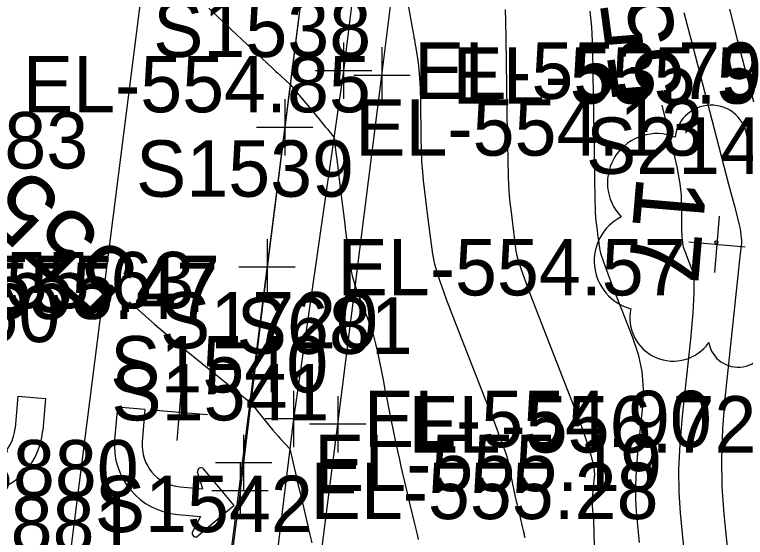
# Model space of a CAD drawing. Extents: x 1724534 to 1727318, y 657156 to 660047.
# Drawn here: x 1725449.4 to 1725501.3, y 658904.2 to 658941.3 of the extents above; entities that cross this region are included whole.
import ezdxf

# ---------------------------------------------------------------- set-up
doc = ezdxf.new("R2010")
doc.units = 0
for name, color, linetype in [('SURVEY - CENTERLINE - Preliminary', 7, 'Continuous'), ('SURVEY - CONTOURS - Index with Text', 7, 'Continuous'), ('SURVEY - CONTOURS - Intermediate with optional Text', 7, 'Continuous'), ('SURVEY - DTM - Breaklines - Points - Elevations', 7, 'Continuous'), ('SURVEY - ROADSIDE BARRIERS - Points - Elevations', 7, 'Continuous'), ('SURVEY - ROADSIDE BARRIERS - Points - Locators', 7, 'Continuous'), ('SURVEY - ROADSIDE BARRIERS - Points - Numbers', 7, 'Continuous'), ('SURVEY - ROADSIDE BARRIERS with Text', 7, 'Continuous'), ('SURVEY - TRAFFIC CONTROL - Pavement Marking - Points - Locators', 7, 'Continuous'), ('SURVEY - TRAFFIC CONTROL - Pavement Marking - Points - Numbers', 7, 'Continuous'), ('SURVEY - TRAFFIC CONTROL - Pavement Marking with Text', 7, 'Continuous'), ('SURVEY - TRANSPORTATION - Features', 7, 'Continuous'), ('SURVEY - TRANSPORTATION - Features - Points - Elevations', 7, 'Continuous'), ('SURVEY - TRANSPORTATION - Features - Points - Locators', 7, 'Continuous'), ('SURVEY - TRANSPORTATION - Features - Points - Numbers', 7, 'Continuous'), ('SURVEY - TRANSPORTATION - Roads', 7, 'Continuous'), ('SURVEY - TRANSPORTATION - Roads - Points - Elevations', 7, 'Continuous'), ('SURVEY - TRANSPORTATION - Roads - Points - Locators', 7, 'Continuous'), ('SURVEY - TRANSPORTATION - Roads - Points - Numbers', 7, 'Continuous'), ('SURVEY - VEGETATION - Features - Points - Locators', 7, 'Continuous'), ('SURVEY - VEGETATION - Features - Points - Numbers', 7, 'Continuous'), ('SURVEY - VEGETATION - Features with Text', 7, 'Continuous')]:
    doc.layers.add(name, color=color, linetype=linetype)

msp = doc.modelspace()

# ---------------------------------------------------------------- linework, layer by layer
at = {"layer": 'SURVEY - CENTERLINE - Preliminary'}
msp.add_line((1725473.744, 658974.019), (1725452.779, 658808.398), dxfattribs=at)
msp.add_line((1725473.744, 658974.019), (1725452.779, 658808.398), dxfattribs=at)
msp.add_line((1725473.744, 658974.019), (1725452.779, 658808.398), dxfattribs=at)
at = {"layer": 'SURVEY - CONTOURS - Index with Text'}
for points in [[(1725495.341, 658934.883), (1725495.52, 658934.199), (1725496.034, 658932.156), (1725496.404, 658930.526), (1725496.629, 658929.307), (1725496.71, 658928.501), (1725496.731, 658926.9), (1725496.739, 658926.366), (1725496.748, 658925.965), (1725496.756, 658925.696), (1725496.765, 658925.56), (1725496.788, 658925.373), (1725496.796, 658925.304), (1725496.805, 658925.237), (1725496.813, 658925.171), (1725496.821, 658925.106), (1725496.842, 658924.937), (1725496.866, 658924.836), (1725496.924, 658924.661), (1725497.015, 658924.412), (1725497.14, 658924.089), (1725497.517, 658923.127), (1725497.614, 658922.555), (1725497.621, 658921.56), (1725497.539, 658920.141), (1725497.368, 658918.299), (1725496.791, 658912.822), (1725496.619, 658910.853), (1725496.536, 658909.055), (1725496.541, 658907.427), (1725496.635, 658905.969), (1725497.003, 658902.309)], [(1725457.569, 658920.947), (1725457.88, 658920.671), (1725458.905, 658919.754), (1725459.363, 658919.354), (1725459.97, 658918.841), (1725460.725, 658918.216), (1725461.628, 658917.477), (1725466.188, 658913.767), (1725466.265, 658913.676), (1725466.305, 658913.627), (1725466.33, 658913.596), (1725466.359, 658913.56), (1725466.44, 658913.459), (1725466.495, 658913.392), (1725466.748, 658913.079), (1725466.948, 658912.835), (1725467.543, 658912.104), (1725467.756, 658911.845), (1725467.95, 658911.614), (1725468.124, 658911.413), (1725468.278, 658911.241), (1725468.949, 658910.506), (1725469.428, 658908.472), (1725469.538, 658908.007), (1725469.661, 658907.486), (1725469.947, 658906.27), (1725470.365, 658904.497), (1725470.519, 658903.845)]]:
    msp.add_lwpolyline(points, dxfattribs=at)
at = {"layer": 'SURVEY - CONTOURS - Intermediate with optional Text'}
for points in [[(1725463.207, 658941.77), (1725463.749, 658941.254), (1725464.407, 658940.636), (1725466.316, 658938.85), (1725466.947, 658938.259), (1725467.41, 658937.825), (1725467.704, 658937.549), (1725467.83, 658937.429), (1725467.993, 658937.267), (1725468.073, 658937.192), (1725468.31, 658936.973), (1725468.981, 658936.357), (1725470.7, 658934.301), (1725471.034, 658933.901), (1725471.301, 658933.581), (1725471.5, 658933.342), (1725471.632, 658933.183), (1725472.09, 658932.63), (1725472.111, 658932.501), (1725472.115, 658932.476), (1725472.118, 658932.455), (1725472.121, 658932.399), (1725472.133, 658932.296), (1725472.226, 658931.529), (1725472.308, 658930.865), (1725472.558, 658928.845), (1725472.651, 658928.097), (1725472.741, 658927.366), (1725472.829, 658926.652), (1725472.916, 658925.955), (1725473.142, 658924.12), (1725473.247, 658923.442), (1725473.39, 658922.783), (1725473.571, 658922.144), (1725473.791, 658921.524), (1725474.429, 658919.897), (1725474.656, 658919.275), (1725474.859, 658918.631), (1725475.037, 658917.964), (1725475.191, 658917.274), (1725475.569, 658915.404), (1725475.707, 658914.719), (1725475.839, 658914.067), (1725475.963, 658913.449), (1725476.082, 658912.863), (1725476.388, 658911.346), (1725476.503, 658910.789), (1725476.616, 658910.255), (1725476.729, 658909.745), (1725476.842, 658909.259), (1725477.354, 658907.083), (1725477.455, 658906.657), (1725477.8, 658905.193), (1725477.891, 658904.803), (1725477.98, 658904.429), (1725478.064, 658904.07)], [(1725477.354, 658941.999), (1725477.713, 658939.996), (1725477.746, 658939.815), (1725477.757, 658939.751), (1725477.766, 658939.701), (1725477.79, 658939.55), (1725477.831, 658939.3), (1725477.888, 658938.951), (1725478.062, 658937.886), (1725478.12, 658937.417), (1725478.166, 658936.808), (1725478.198, 658936.061), (1725478.218, 658935.174), (1725478.252, 658932.623), (1725478.272, 658931.713), (1725478.307, 658930.895), (1725478.358, 658930.17), (1725478.422, 658929.539), (1725478.687, 658927.399), (1725478.757, 658926.833), (1725478.825, 658926.281), (1725478.892, 658925.743), (1725479.067, 658924.324), (1725479.22, 658923.615), (1725479.548, 658922.552), (1725480.051, 658921.134), (1725480.728, 658919.361), (1725482.767, 658914.161), (1725483.442, 658912.426), (1725483.937, 658911.122), (1725484.253, 658910.249), (1725484.388, 658909.806), (1725484.511, 658909.2), (1725484.598, 658908.766), (1725484.639, 658908.566), (1725484.677, 658908.376), (1725484.777, 658907.884), (1725484.814, 658907.703), (1725484.851, 658907.53), (1725484.887, 658907.365), (1725484.924, 658907.207), (1725485.02, 658906.797), (1725485.056, 658906.646), (1725485.09, 658906.501), (1725485.234, 658905.888), (1725485.264, 658905.762), (1725485.32, 658905.524), (1725485.347, 658905.412), (1725485.415, 658905.121), (1725485.44, 658905.014), (1725485.465, 658904.91), (1725485.488, 658904.811), (1725485.511, 658904.715), (1725485.57, 658904.465), (1725485.592, 658904.373), (1725485.613, 658904.283), (1725485.633, 658904.197)], [(1725484.238, 658941.672), (1725484.264, 658940.857), (1725484.29, 658939.607), (1725484.315, 658937.922), (1725484.383, 658932.846), (1725484.412, 658931.129), (1725484.447, 658929.784), (1725484.489, 658928.812), (1725484.536, 658928.212), (1725484.673, 658927.109), (1725484.723, 658926.7), (1725484.773, 658926.301), (1725484.821, 658925.911), (1725484.868, 658925.531), (1725484.992, 658924.529), (1725485.137, 658923.933), (1725485.48, 658922.899), (1725486.02, 658921.425), (1725486.757, 658919.512), (1725488.987, 658913.826), (1725489.713, 658911.907), (1725490.219, 658910.416), (1725490.505, 658909.351), (1725490.57, 658908.714), (1725490.451, 658907.584), (1725490.416, 658907.178), (1725490.399, 658906.807), (1725490.4, 658906.471), (1725490.419, 658906.17), (1725490.495, 658905.415), (1725490.526, 658904.567), (1725490.559, 658902.589)], [(1725500.137, 658941.703), (1725500.695, 658939.549), (1725502.386, 658933.071)], [(1725490.249, 658941.558), (1725490.348, 658940.439), (1725490.419, 658938.937), (1725490.461, 658937.053), (1725490.535, 658931.52), (1725490.563, 658929.674), (1725490.592, 658928.286), (1725490.621, 658927.357), (1725490.651, 658926.886), (1725490.76, 658926.002), (1725490.789, 658925.769), (1725490.817, 658925.541), (1725490.844, 658925.318), (1725490.917, 658924.733), (1725491.002, 658924.385), (1725491.202, 658923.78), (1725491.518, 658922.919), (1725491.949, 658921.801), (1725493.252, 658918.477), (1725493.664, 658917.231), (1725493.92, 658915.988), (1725494.022, 658914.746), (1725493.969, 658913.506), (1725493.621, 658910.203), (1725493.517, 658909.015), (1725493.467, 658907.931), (1725493.47, 658906.949), (1725493.527, 658906.07), (1725493.749, 658903.862)], [(1725496.909, 658941.476), (1725497.54, 658939.048), (1725500.084, 658929.298), (1725500.535, 658927.56), (1725500.808, 658926.498), (1725500.903, 658926.111), (1725500.93, 658925.885), (1725500.935, 658925.836), (1725500.941, 658925.788), (1725500.957, 658925.659), (1725500.974, 658925.514), (1725500.979, 658925.466), (1725500.995, 658925.338), (1725500.998, 658925.277), (1725500.995, 658925.192), (1725500.986, 658925.083), (1725500.971, 658924.95), (1725500.925, 658924.561), (1725500.881, 658924.16), (1725500.784, 658923.25), (1725499.817, 658914.073), (1725499.64, 658911.922), (1725499.568, 658909.837), (1725499.603, 658907.82), (1725499.743, 658905.869), (1725500.257, 658900.756)]]:
    msp.add_lwpolyline(points, dxfattribs=at)
at = {"layer": 'SURVEY - ROADSIDE BARRIERS - Points - Locators'}
for p, q in [((1725475.489, 658938.998), (1725475.489, 658934.998)), ((1725477.489, 658936.998), (1725473.489, 658936.998)), ((1725472.364, 658914.252), (1725472.364, 658910.252)), ((1725474.364, 658912.252), (1725470.364, 658912.252))]:
    msp.add_line(p, q, dxfattribs=at)
at = {"layer": 'SURVEY - ROADSIDE BARRIERS with Text'}
msp.add_lwpolyline([(1725454.307, 658763.664), (1725456.988, 658788.398), (1725459.975, 658813.106), (1725462.961, 658837.817), (1725466.031, 658862.66), (1725469.198, 658887.437), (1725472.364, 658912.252), (1725475.489, 658936.998), (1725478.578, 658961.799), (1725481.795, 658986.471), (1725485.277, 659011.185), (1725489.239, 659035.685), (1725493.561, 659060.194), (1725498.271, 659084.816), (1725503.177, 659108.92), (1725508.576, 659133.257), (1725514.221, 659157.599), (1725521.221, 659181.564), (1725529.697, 659209.302)], dxfattribs=at)
at = {"layer": 'SURVEY - TRAFFIC CONTROL - Pavement Marking - Points - Locators'}
for p, q in [((1725460.967, 658911.093), (1725461.305, 658915.079)), ((1725463.129, 658912.917), (1725459.143, 658913.255))]:
    msp.add_line(p, q, dxfattribs=at)
at = {"layer": 'SURVEY - TRAFFIC CONTROL - Pavement Marking with Text'}
for p, q in [((1725449.674, 658914.26), (1725449.48, 658911.972)), ((1725449.674, 658914.26), (1725451.635, 658914.093)), ((1725451.635, 658914.093), (1725451.441, 658911.806)), ((1725456.724, 658913.461), (1725456.53, 658911.173)), ((1725458.685, 658913.294), (1725456.724, 658913.461)), ((1725458.685, 658913.294), (1725458.491, 658911.006)), ((1725465.021, 658906.502), (1725462.843, 658909.083)), ((1725462.793, 658907.678), (1725462.421, 658908.85)), ((1725461.182, 658907.815), (1725462.793, 658907.678)), ((1725465.021, 658906.502), (1725462.439, 658904.324)), ((1725461.016, 658905.854), (1725462.628, 658905.717)), ((1725462.628, 658905.717), (1725462.062, 658904.625))]:
    msp.add_line(p, q, dxfattribs=at)
msp.add_lwpolyline([(1725460.313, 658957.642), (1725453.259, 658902.135), (1725452.764, 658898.17), (1725443.879, 658826.783), (1725443.64, 658824.8), (1725439.422, 658789.083), (1725439.193, 658787.097), (1725436.275, 658761.27), (1725433.358, 658735.444), (1725431.642, 658719.312)], dxfattribs=at)
for centre, radius, start, end in [((1725446.538, 658912.222), 4.92, 265.1461, 355.1461), ((1725446.538, 658912.222), 2.952, 265.1461, 355.1461), ((1725461.432, 658910.757), 4.92, 175.1461, 265.1461), ((1725461.432, 658910.757), 2.952, 175.1461, 265.1461), ((1725462.655, 658908.925), 0.246, 40.1461, 197.6393), ((1725462.281, 658904.512), 0.246, 152.6979, 310.1461)]:
    msp.add_arc(centre, radius, start, end, dxfattribs=at)
at = {"layer": 'SURVEY - TRANSPORTATION - Features'}
msp.add_lwpolyline([(1725475.825, 658962.14), (1725472.769, 658937.341), (1725469.208, 658912.632), (1725466.187, 658887.82), (1725463.008, 658863.047), (1725460.29, 658838.183), (1725456.884, 658813.49), (1725454.083, 658788.722), (1725451.229, 658763.96), (1725449.904, 658751.509), (1725447.7, 658726.64), (1725444.57, 658701.814), (1725442.188, 658676.935)], dxfattribs=at)
at = {"layer": 'SURVEY - TRANSPORTATION - Features - Points - Locators'}
for p, q in [((1725472.769, 658939.341), (1725472.769, 658935.341)), ((1725474.769, 658937.341), (1725470.769, 658937.341)), ((1725469.208, 658914.632), (1725469.208, 658910.632)), ((1725471.208, 658912.632), (1725467.208, 658912.632))]:
    msp.add_line(p, q, dxfattribs=at)
at = {"layer": 'SURVEY - TRANSPORTATION - Roads'}
msp.add_lwpolyline([(1725470.348, 658947.189), (1725468.597, 658933.312), (1725467.348, 658923.398), (1725465.675, 658909.512), (1725465.425, 658907.529), (1725464.411, 658899.602), (1725462.646, 658885.729), (1725459.817, 658863.933), (1725459.564, 658861.952), (1725457.312, 658844.112), (1725457.049, 658842.132), (1725454.877, 658826.297), (1725454.612, 658824.317), (1725452.888, 658810.439), (1725452.647, 658808.456), (1725449.994, 658784.63)], dxfattribs=at)
at = {"layer": 'SURVEY - TRANSPORTATION - Roads - Points - Locators'}
for p, q in [((1725468.597, 658935.312), (1725468.597, 658931.312)), ((1725470.597, 658933.312), (1725466.597, 658933.312)), ((1725467.348, 658925.398), (1725467.348, 658921.398)), ((1725469.348, 658923.398), (1725465.348, 658923.398)), ((1725465.675, 658911.512), (1725465.675, 658907.512)), ((1725467.675, 658909.512), (1725463.675, 658909.512)), ((1725465.425, 658909.529), (1725465.425, 658905.529)), ((1725467.425, 658907.529), (1725463.425, 658907.529))]:
    msp.add_line(p, q, dxfattribs=at)
at = {"layer": 'SURVEY - VEGETATION - Features - Points - Locators'}
for p, q in [((1725499.422, 658927.013), (1725499.084, 658923.027)), ((1725497.26, 658925.189), (1725501.246, 658924.851))]:
    msp.add_line(p, q, dxfattribs=at)
at = {"layer": 'SURVEY - VEGETATION - Features with Text'}
msp.add_circle((1725499.209, 658925.169), 0.108, dxfattribs=at)
for centre, radius, start, end in [((1725498.845, 658932.321), 2.575, 358.2631, 173.2634), ((1725494.981, 658929.386), 3.491, 68.0102, 223.8487), ((1725494.065, 658923.84), 3.514, 117.1144, 254.6386), ((1725496.152, 658919.821), 3.084, 168.0616, 324.8506), ((1725500.757, 658918.42), 2.117, 190.1778, 8.9234)]:
    msp.add_arc(centre, radius, start, end, dxfattribs=at)

# ---------------------------------------------------------------- texts
at = {"layer": 'SURVEY - CONTOURS - Index with Text'}
for s, rotation, p in [('550', 97.7093, (1725496.858, 658935.592)), ('555', 138.4329, (1725458.58, 658923.244))]:
    msp.add_text(s, height=5, rotation=rotation, dxfattribs=at).set_placement(p)
at = {"layer": 'SURVEY - DTM - Breaklines - Points - Elevations'}
for s, p in [('EL-555.83', (1725429.973, 658930.403)), ('EL-555.63', (1725437.503, 658920.481)), ('EL-555.47', (1725439.197, 658919.722))]:
    msp.add_text(s, height=4, dxfattribs=at).set_placement(p)
at = {"layer": 'SURVEY - ROADSIDE BARRIERS - Points - Elevations'}
for s, p in [('EL-555.55', (1725480.489, 658934.998)), ('EL-556.72', (1725477.364, 658910.252))]:
    msp.add_text(s, height=4, dxfattribs=at).set_placement(p)
at = {"layer": 'SURVEY - ROADSIDE BARRIERS - Points - Numbers'}
msp.add_text('S681', height=4, dxfattribs=at).set_placement((1725465.186, 658917.252))
at = {"layer": 'SURVEY - TRAFFIC CONTROL - Pavement Marking - Points - Numbers'}
for s, p in [('S2060', (1725437.214, 658918.086)), ('S880', (1725445.75, 658907.135)), ('S881', (1725445.586, 658903.17))]:
    msp.add_text(s, height=4, dxfattribs=at).set_placement(p)
at = {"layer": 'SURVEY - TRANSPORTATION - Features - Points - Elevations'}
for s, p in [('EL-553.79', (1725477.769, 658935.341)), ('EL-555.47', (1725439.304, 658920.209)), ('EL-555.47', (1725439.197, 658919.722)), ('EL-555.47', (1725439.197, 658919.722)), ('EL-554.90', (1725474.208, 658910.632))]:
    msp.add_text(s, height=4, dxfattribs=at).set_placement(p)
at = {"layer": 'SURVEY - TRANSPORTATION - Features - Points - Numbers'}
msp.add_text('S1720', height=4, dxfattribs=at).set_placement((1725459.747, 658917.632))
at = {"layer": 'SURVEY - TRANSPORTATION - Roads - Points - Elevations'}
for s, p in [('EL-554.85', (1725450.023, 658934.389)), ('EL-554.13', (1725473.597, 658931.312)), ('EL-554.57', (1725472.348, 658921.398)), ('EL-555.19', (1725470.675, 658907.512)), ('EL-555.28', (1725470.425, 658905.529))]:
    msp.add_text(s, height=4, dxfattribs=at).set_placement(p)
at = {"layer": 'SURVEY - TRANSPORTATION - Roads - Points - Numbers'}
for s, p in [('S1538', (1725459.262, 658938.312)), ('S1539', (1725458.045, 658928.398)), ('S1540', (1725456.214, 658914.512)), ('S1541', (1725456.295, 658912.529)), ('S1542', (1725455.123, 658904.602))]:
    msp.add_text(s, height=4, dxfattribs=at).set_placement(p)
at = {"layer": 'SURVEY - VEGETATION - Features - Points - Numbers'}
msp.add_text('S2142', height=4, dxfattribs=at).set_placement((1725489.965, 658930.02))
at = {"layer": 'SURVEY - VEGETATION - Features with Text'}
msp.add_text('17', height=5, rotation=265.1461, dxfattribs=at).set_placement((1725493.561, 658929.95))

doc.saveas('drawing.dxf')
